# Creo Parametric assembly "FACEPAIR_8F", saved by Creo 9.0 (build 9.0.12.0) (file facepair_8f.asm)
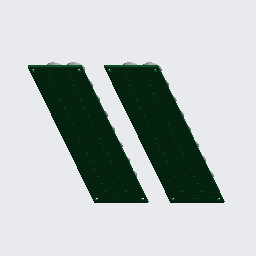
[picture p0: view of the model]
Units: millimeter Newton Second (mmNs); MM, TONNE, SECS

Created from: XX_MMNS_ASM_DESIGN_ABS.ASM

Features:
  1. datum plane "ASM_RIGHT"
  2. datum plane "ASM_TOP"
  3. datum plane "ASM_FRONT"
  4. coordinate system
  5. coordinate system
  6. component "PANEL_8F"
  7. coordinate system
  8. component "PANEL_8F"

Other named items: ACS0, ACS1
